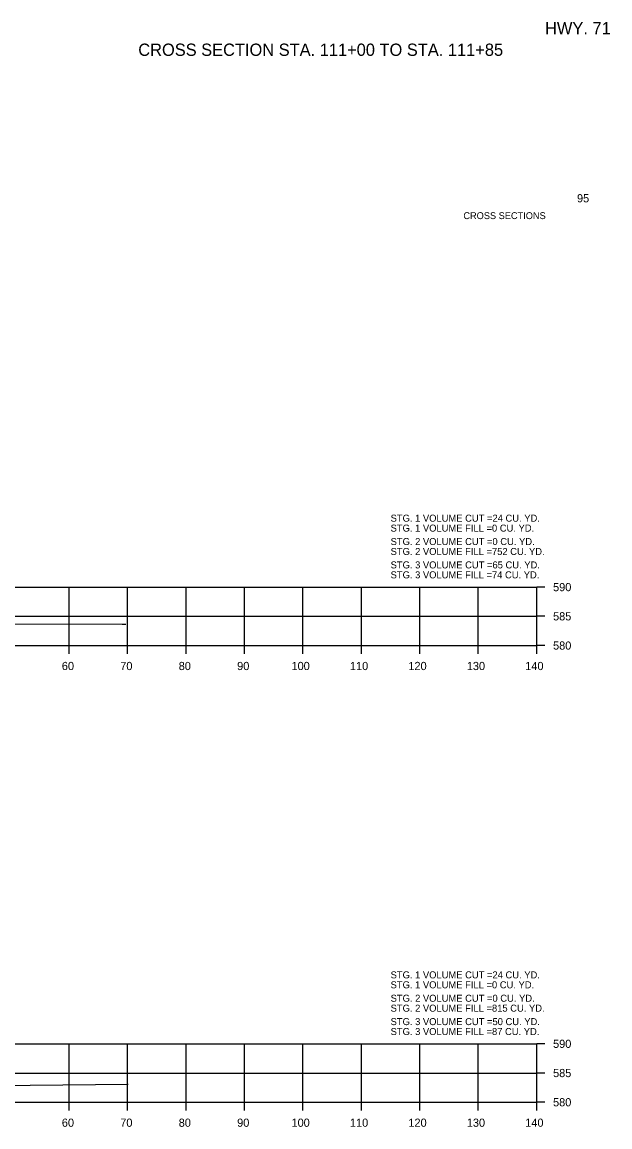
# Model space of a CAD drawing. Extents: x 642114 to 642416, y 286928 to 293347.
# Drawn here: x 642312.2 to 642412.8, y 288743.9 to 288933 of the extents above; entities that cross this region are included whole.
import ezdxf

# ---------------------------------------------------------------- set-up
doc = ezdxf.new("R2010")
doc.units = 0
for name, color, linetype in [('R_Axis', 7, 'Continuous'), ('R_Axis Annot', 7, 'Continuous'), ('R_Border', 7, 'Continuous'), ('R_Border Notes', 7, 'Continuous'), ('R_Draft', 7, 'Continuous'), ('R_Exist Surface Annot', 7, 'Continuous'), ('R_Grid', 7, 'Continuous')]:
    doc.layers.add(name, color=color, linetype=linetype)

msp = doc.modelspace()

# ---------------------------------------------------------------- linework, layer by layer
at = {"layer": 'R_Axis'}
for p, q in [((642400.24, 288826.34), (642400.24, 288836.34)), ((642401.64, 288836.34), (642400.24, 288836.34)), ((642401.64, 288831.34), (642400.24, 288831.34)), ((642120.24, 288826.34), (642400.24, 288826.34)), ((642320.24, 288824.94), (642320.24, 288826.34)), ((642330.24, 288824.94), (642330.24, 288826.34)), ((642340.24, 288824.94), (642340.24, 288826.34)), ((642350.24, 288824.94), (642350.24, 288826.34)), ((642360.24, 288824.94), (642360.24, 288826.34)), ((642370.24, 288824.94), (642370.24, 288826.34)), ((642380.24, 288824.94), (642380.24, 288826.34)), ((642390.24, 288824.94), (642390.24, 288826.34)), ((642400.24, 288824.94), (642400.24, 288826.34)), ((642401.64, 288826.34), (642400.24, 288826.34)), ((642400.24, 288748.17), (642400.24, 288758.17)), ((642401.64, 288758.17), (642400.24, 288758.17)), ((642401.64, 288753.17), (642400.24, 288753.17)), ((642120.24, 288748.17), (642400.24, 288748.17)), ((642320.24, 288746.77), (642320.24, 288748.17)), ((642330.24, 288746.77), (642330.24, 288748.17)), ((642340.24, 288746.77), (642340.24, 288748.17)), ((642350.24, 288746.77), (642350.24, 288748.17)), ((642360.24, 288746.77), (642360.24, 288748.17)), ((642370.24, 288746.77), (642370.24, 288748.17)), ((642380.24, 288746.77), (642380.24, 288748.17)), ((642390.24, 288746.77), (642390.24, 288748.17)), ((642400.24, 288746.77), (642400.24, 288748.17)), ((642401.64, 288748.17), (642400.24, 288748.17))]:
    msp.add_line(p, q, dxfattribs=at)
at = {"layer": 'R_Exist Surface Annot'}
for points in [[(642120.24, 288828.52), (642123.8, 288828.55), (642157.51, 288828.8), (642180.89, 288828.21), (642193.09, 288827.92), (642199.63, 288830.32), (642200.88, 288830.78), (642202.82, 288831.35), (642205, 288832.01), (642211.31, 288832.34), (642211.85, 288832.37), (642212.77, 288832.37), (642223.4, 288832.44), (642224.57, 288832.41), (642234.34, 288832.14), (642241, 288831.8), (642241.63, 288831.77), (642254.02, 288829.29), (642254.68, 288829.17), (642256.71, 288829.22), (642281.06, 288830.08), (642329.31, 288829.99), (642329.95, 288829.99)], [(642120.24, 288748.82), (642164.16, 288749.2), (642190.06, 288748.86), (642197.74, 288748.73), (642198.8, 288749.07), (642205.78, 288751.3), (642207.39, 288751.68), (642209.1, 288752.08), (642209.69, 288752.2), (642210.59, 288752.23), (642216.77, 288752.53), (642218.79, 288752.55), (642228.32, 288752.63), (642237.02, 288752.38), (642239.25, 288752.32), (642245.11, 288751.99), (642246.71, 288751.9), (642258.9, 288748.93), (642260.64, 288748.53), (642267.25, 288749.05), (642287.85, 288750.81), (642313.54, 288751.07), (642330.35, 288751.24)]]:
    msp.add_lwpolyline(points, dxfattribs=at)
at = {"layer": 'R_Grid'}
for p, q in [((642120.24, 288836.34), (642400.24, 288836.34)), ((642320.24, 288826.34), (642320.24, 288836.34)), ((642330.24, 288826.34), (642330.24, 288836.34)), ((642340.24, 288826.34), (642340.24, 288836.34)), ((642350.24, 288826.34), (642350.24, 288836.34)), ((642360.24, 288826.34), (642360.24, 288836.34)), ((642370.24, 288826.34), (642370.24, 288836.34)), ((642380.24, 288826.34), (642380.24, 288836.34)), ((642390.24, 288826.34), (642390.24, 288836.34)), ((642400.24, 288826.34), (642400.24, 288836.34)), ((642120.24, 288831.34), (642400.24, 288831.34)), ((642120.24, 288826.34), (642400.24, 288826.34)), ((642120.24, 288758.17), (642400.24, 288758.17)), ((642320.24, 288748.17), (642320.24, 288758.17)), ((642330.24, 288748.17), (642330.24, 288758.17)), ((642340.24, 288748.17), (642340.24, 288758.17)), ((642350.24, 288748.17), (642350.24, 288758.17)), ((642360.24, 288748.17), (642360.24, 288758.17)), ((642370.24, 288748.17), (642370.24, 288758.17)), ((642380.24, 288748.17), (642380.24, 288758.17)), ((642390.24, 288748.17), (642390.24, 288758.17)), ((642400.24, 288748.17), (642400.24, 288758.17)), ((642120.24, 288753.17), (642400.24, 288753.17)), ((642120.24, 288748.17), (642400.24, 288748.17))]:
    msp.add_line(p, q, dxfattribs=at)

# ---------------------------------------------------------------- texts
at = {"layer": 'R_Axis Annot'}
for s, height, p in [('HWY. 71', 2.1, (642401.67, 288930.95)), ('CROSS SECTION STA. 111+00 TO STA. 111+85', 2.1, (642332.06, 288927.27)), ('590', 1.4, (642403.04, 288835.64)), ('585', 1.4, (642403.04, 288830.64)), ('580', 1.4, (642403.04, 288825.64)), ('60', 1.4, (642318.98, 288822.14)), ('70', 1.4, (642328.98, 288822.14)), ('80', 1.4, (642338.98, 288822.14)), ('90', 1.4, (642348.98, 288822.14)), ('100', 1.4, (642358.28, 288822.14)), ('110', 1.4, (642368.28, 288822.14)), ('120', 1.4, (642378.28, 288822.14)), ('130', 1.4, (642388.28, 288822.14)), ('140', 1.4, (642398.28, 288822.14)), ('590', 1.4, (642403.04, 288757.47)), ('585', 1.4, (642403.04, 288752.47)), ('580', 1.4, (642403.04, 288747.47)), ('60', 1.4, (642318.98, 288743.97)), ('70', 1.4, (642328.98, 288743.97)), ('80', 1.4, (642338.98, 288743.97)), ('90', 1.4, (642348.98, 288743.97)), ('100', 1.4, (642358.28, 288743.97)), ('110', 1.4, (642368.28, 288743.97)), ('120', 1.4, (642378.28, 288743.97)), ('130', 1.4, (642388.28, 288743.97)), ('140', 1.4, (642398.28, 288743.97))]:
    msp.add_text(s, height=height, dxfattribs=at).set_placement(p)
at = {"layer": 'R_Border'}
msp.add_text('95', height=1.4, dxfattribs=at).set_placement((642407.14, 288902.2))
at = {"layer": 'R_Border Notes'}
msp.add_text('    CROSS SECTIONS    ', height=1.178, dxfattribs=at).set_placement((642385.94, 288899.33))
at = {"layer": 'R_Draft'}
for s, p in [('STG. 1 VOLUME CUT =24 CU. YD.', (642375.24, 288847.54)), ('STG. 1 VOLUME FILL =0 CU. YD.', (642375.24, 288845.84)), ('STG. 2 VOLUME CUT =0 CU. YD.', (642375.24, 288843.54)), ('STG. 2 VOLUME FILL =752 CU. YD.', (642375.24, 288841.84)), ('STG. 3 VOLUME CUT =65 CU. YD.', (642375.24, 288839.54)), ('STG. 3 VOLUME FILL =74 CU. YD.', (642375.24, 288837.84)), ('STG. 1 VOLUME CUT =24 CU. YD.', (642375.24, 288769.37)), ('STG. 1 VOLUME FILL =0 CU. YD.', (642375.24, 288767.67)), ('STG. 2 VOLUME CUT =0 CU. YD.', (642375.24, 288765.37)), ('STG. 2 VOLUME FILL =815 CU. YD.', (642375.24, 288763.67)), ('STG. 3 VOLUME CUT =50 CU. YD.', (642375.24, 288761.37)), ('STG. 3 VOLUME FILL =87 CU. YD.', (642375.24, 288759.67))]:
    msp.add_text(s, height=1.2, dxfattribs=at).set_placement(p)

doc.saveas('drawing.dxf')
